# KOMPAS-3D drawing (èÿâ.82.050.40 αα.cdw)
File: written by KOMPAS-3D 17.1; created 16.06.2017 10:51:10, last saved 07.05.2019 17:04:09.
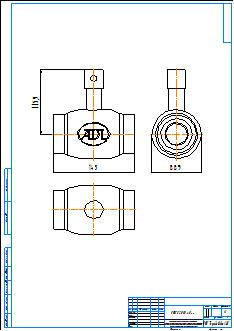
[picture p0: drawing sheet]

Sheet 1: A2, portrait

Title block, sheet 1: name: КШГ.82.050.40 рр; material: Внимание! Данный продукт является объектом авторского права ООО «Торговый Дом АДЛ». / Запрещается изменение, копирование, распространение / (в том числе путем копирования на другие сайты и ресурсы в Интернете) / или любое иное использование информации и объектов без предварительного / согласия правообладателя (ООО «Торговый Дом АДЛ»).; scale: 1:1; sheets: 1; organisation: ООО "Торговый дом АДЛ"; sheet format: A2; stored path: C:\Users\tra\Desktop\2д чертежи\Шаровые краны БИВАЛ\КШ_Бивал_серия_82_85\KOMPAS 2D\КШГ.82.050.40 рр.cdw

Views: Спереди 1, Проекционный вид 2, Проекционный вид 3
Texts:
  Klimkovich
  ADL
Dimensions and other numbers on the sheet: 145; 115,9; 88,9; 1:1; 1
